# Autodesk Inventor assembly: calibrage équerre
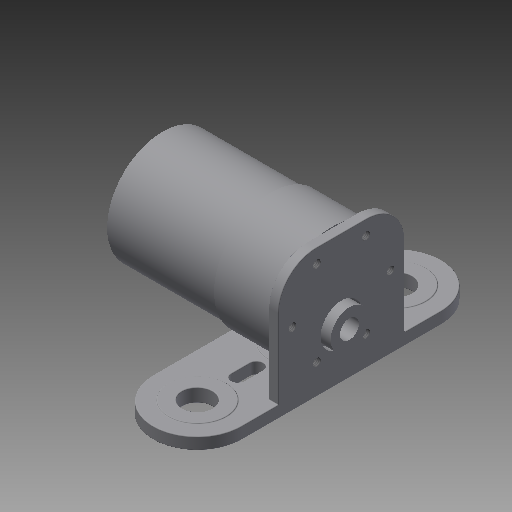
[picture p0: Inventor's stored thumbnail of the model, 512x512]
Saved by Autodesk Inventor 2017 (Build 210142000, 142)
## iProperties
Part Number: calibrage équerre
Material: Générique
Document SubType Name: Assembly
Designer: ficho
Author: ficho
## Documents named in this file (3)
- G:\travail\année 2017-2018\1STI2D\challenge\adaptation moteur.iam
- G:\travail\année 2017-2018\1STI2D\challenge\corps moto reducteur.ipt
- G:\travail\année 2017-2018\1STI2D\challenge\équerre meccano pour motoréducteur conrad motocraft.ipt
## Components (2 placed, 2 different names)
1. corps moto reducteur:1 — Logement:1, Placage:1
2. équerre meccano pour motoréducteur conrad motocraft:1 — Logement:1, Placage:1
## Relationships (2: Insert 1, Mate 1)
- Logement:1 [Insert]: corps moto reducteur:1 ↔ équerre meccano pour motoréducteur conrad motocraft:1
- Placage:1 [Mate]: corps moto reducteur:1 ↔ équerre meccano pour motoréducteur conrad motocraft:1
